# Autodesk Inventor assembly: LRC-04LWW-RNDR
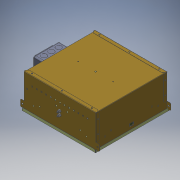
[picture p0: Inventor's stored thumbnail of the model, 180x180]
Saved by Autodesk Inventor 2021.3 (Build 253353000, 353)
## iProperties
load_classification: Lighting
motor: 0 ul
Part Number: LRC-04LWW-RNDR
Document SubType Name: Assembly
Designer: JChurch
description: 0:0:Lensed 4" Wall Wash - COB LED
manufacturer: 0:0:The Kirlin Company
model: 0:0:LRC-04LWW
url: 0:0:
Author: JChurch
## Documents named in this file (6)
- X:\Revit Files\0000-Un-Zipped\COB\LRC-04LWW-RND\LRC-04LWW-RNDR.iam
- X:\INVENTOR\830\830520-00-00.ipt
- X:\INVENTOR\881\881088-00-00.iam
- X:\INVENTOR\750\750460-00-XX.iam
- X:\INVENTOR\725\725377-01-00.ipt
- X:\Revit Files\0000-Un-Zipped\COB\LRC-04LWW-RND\LRC-04LWW-RNDR_Substitute_1.ipt
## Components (5 placed, 5 different names)
1. 830520-00-00:1 — Mate:1, Mate:2, Mate:3, Mate:4, Tangent:1, Angle:1, Insert:1
2. 881088-00-00:1 [sub-assembly] — Mate:4, Tangent:1, Angle:1
3. 750460-00-XX:1 [sub-assembly] — Insert:1, Flush:1, Mate:5, Mate:6
4. 725377-01-00:1 — Mate:5, Mate:6
5. LRC-04LWW-RNDR_Substitute_1:1
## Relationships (10: Mate 6, Tangent 1, Angle 1, Insert 1, Flush 1)
- Mate:1: 830520-00-00:1
- Mate:2: 830520-00-00:1
- Mate:3: 830520-00-00:1
- Mate:4: 830520-00-00:1 ↔ 881088-00-00:1
- Tangent:1: 830520-00-00:1 ↔ 881088-00-00:1
- Angle:1: 830520-00-00:1 ↔ 881088-00-00:1
- Insert:1: 830520-00-00:1 ↔ 750460-00-XX:1
- Flush:1: 750460-00-XX:1
- Mate:5: 750460-00-XX:1 ↔ 725377-01-00:1
- Mate:6: 750460-00-XX:1 ↔ 725377-01-00:1
